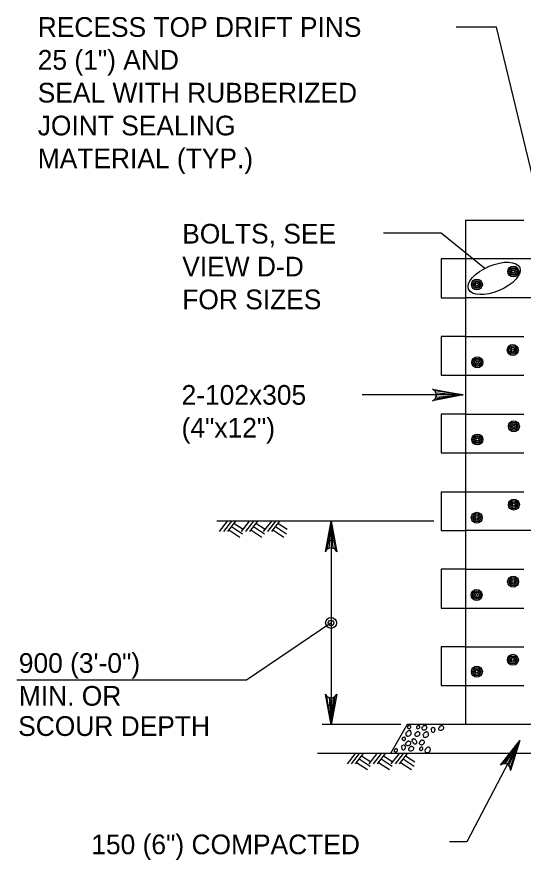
# Model space of a CAD drawing. Extents: x 638142 to 639291, y 297247 to 298438.
# Drawn here: x 638829.2 to 638906.2, y 297993.6 to 298121.9 of the extents above; entities that cross this region are included whole.
import ezdxf

# ---------------------------------------------------------------- set-up
doc = ezdxf.new("R2010")
doc.units = 0
doc.layers.add('3', color=7, linetype='Continuous')
doc.layers.add('5', color=7, linetype='Continuous')

msp = doc.modelspace()

# ---------------------------------------------------------------- linework, layer by layer
at = {"layer": '3'}
for p, q in [((638897.44, 298091), (638906.3, 298091)), ((638897.44, 298091), (638897.44, 298014.22)), ((638897.44, 298085.09), (638893.75, 298085.09)), ((638893.75, 298085.09), (638893.75, 298079.18)), ((638912.21, 298085.09), (638897.44, 298085.09)), ((638893.75, 298079.18), (638897.44, 298079.18)), ((638912.21, 298079.18), (638897.44, 298079.18)), ((638893.75, 298073.28), (638893.75, 298067.37)), ((638897.44, 298073.28), (638893.75, 298073.28)), ((638897.44, 298073.28), (638906.3, 298073.28)), ((638893.75, 298067.37), (638897.44, 298067.37)), ((638897.44, 298067.37), (638906.3, 298067.37)), ((638897.44, 298061.47), (638893.75, 298061.47)), ((638893.75, 298061.47), (638893.75, 298055.56)), ((638897.44, 298061.47), (638906.3, 298061.47)), ((638893.75, 298055.56), (638897.44, 298055.56)), ((638897.44, 298055.56), (638906.3, 298055.56)), ((638893.75, 298049.65), (638893.75, 298043.75)), ((638893.75, 298049.65), (638897.44, 298049.65)), ((638897.44, 298049.65), (638906.3, 298049.65)), ((638892.62, 298045.18), (638859.61, 298045.18)), ((638861.19, 298045.18), (638859.97, 298043.59)), ((638861.82, 298045.18), (638860.6, 298043.59)), ((638862.45, 298045.18), (638861.23, 298043.59)), ((638864.54, 298045.18), (638863.32, 298043.59)), ((638865.17, 298045.18), (638863.95, 298043.59)), ((638865.8, 298045.18), (638864.58, 298043.59)), ((638867.89, 298045.18), (638866.67, 298043.59)), ((638868.52, 298045.18), (638867.29, 298043.59)), ((638869.15, 298045.18), (638867.93, 298043.59)), ((638861.81, 298044.35), (638863.49, 298043.25)), ((638862.2, 298044.85), (638863.58, 298043.94)), ((638865.16, 298044.35), (638866.83, 298043.25)), ((638865.54, 298044.85), (638866.93, 298043.94)), ((638868.51, 298044.35), (638870.18, 298043.25)), ((638868.89, 298044.85), (638870.28, 298043.94)), ((638861.43, 298043.85), (638863.1, 298042.75)), ((638864.77, 298043.85), (638866.45, 298042.75)), ((638868.12, 298043.85), (638869.79, 298042.75)), ((638893.75, 298043.75), (638897.44, 298043.75)), ((638912.21, 298043.75), (638897.44, 298043.75)), ((638897.44, 298037.84), (638893.75, 298037.84)), ((638893.75, 298037.84), (638893.75, 298031.94)), ((638897.44, 298037.84), (638906.3, 298037.84)), ((638893.75, 298031.94), (638897.44, 298031.94)), ((638897.44, 298031.94), (638906.3, 298031.94)), ((638893.75, 298026.03), (638893.75, 298020.13)), ((638897.44, 298026.03), (638893.75, 298026.03)), ((638897.44, 298026.03), (638906.3, 298026.03)), ((638893.75, 298020.13), (638897.44, 298020.13)), ((638897.44, 298020.13), (638906.3, 298020.13)), ((638888.58, 298014.22), (638886.02, 298009.79)), ((638987.5, 298014.22), (638888.58, 298014.22)), ((639000.21, 298009.79), (638874.92, 298009.79)), ((638880.63, 298009.79), (638879.41, 298008.2)), ((638881.26, 298009.79), (638880.04, 298008.2)), ((638881.89, 298009.79), (638880.67, 298008.2)), ((638881.63, 298009.46), (638883.02, 298008.54)), ((638883.97, 298009.79), (638882.75, 298008.2)), ((638884.6, 298009.79), (638883.38, 298008.2)), ((638885.23, 298009.79), (638884.01, 298008.2)), ((638884.98, 298009.46), (638886.36, 298008.54)), ((638887.32, 298009.79), (638886.1, 298008.2)), ((638887.95, 298009.79), (638886.73, 298008.2)), ((638888.58, 298009.79), (638887.36, 298008.2)), ((638888.32, 298009.46), (638889.71, 298008.54)), ((638880.86, 298008.45), (638882.54, 298007.35)), ((638881.25, 298008.96), (638882.92, 298007.86)), ((638884.21, 298008.45), (638885.88, 298007.35)), ((638884.59, 298008.96), (638886.27, 298007.86)), ((638887.56, 298008.45), (638889.23, 298007.35)), ((638887.94, 298008.96), (638889.61, 298007.86))]:
    msp.add_line(p, q, dxfattribs=at)
for centre, radius in [((638904.71, 298083.18), 0.833), ((638904.71, 298083.18), 0.625), ((638904.71, 298083.18), 0.417), ((638904.71, 298083.18), 0.208), ((638899.17, 298081.2), 0.833), ((638899.17, 298081.2), 0.625), ((638899.17, 298081.2), 0.417), ((638899.17, 298081.2), 0.208), ((638904.63, 298071.22), 0.833), ((638904.63, 298071.22), 0.625), ((638904.63, 298071.22), 0.417), ((638904.63, 298071.22), 0.208), ((638899.24, 298069.35), 0.833), ((638899.24, 298069.35), 0.625), ((638899.24, 298069.35), 0.417), ((638899.24, 298069.35), 0.208), ((638904.8, 298059.6), 0.833), ((638904.8, 298059.6), 0.625), ((638904.8, 298059.6), 0.417), ((638904.8, 298059.6), 0.208), ((638899.24, 298057.6), 0.833), ((638899.24, 298057.6), 0.625), ((638899.24, 298057.6), 0.417), ((638899.24, 298057.6), 0.208), ((638904.8, 298047.69), 0.833), ((638904.8, 298047.69), 0.625), ((638904.8, 298047.69), 0.417), ((638904.8, 298047.69), 0.208), ((638899.16, 298045.69), 0.833), ((638899.16, 298045.69), 0.625), ((638899.16, 298045.69), 0.417), ((638899.16, 298045.69), 0.208), ((638904.69, 298035.95), 0.833), ((638904.69, 298035.95), 0.625), ((638904.69, 298035.95), 0.417), ((638904.69, 298035.95), 0.208), ((638899.13, 298033.93), 0.833), ((638899.13, 298033.93), 0.625), ((638899.13, 298033.93), 0.417), ((638899.13, 298033.93), 0.208), ((638904.65, 298024.06), 0.833), ((638904.65, 298024.06), 0.625), ((638904.65, 298024.06), 0.417), ((638904.65, 298024.06), 0.208), ((638899.17, 298022.26), 0.833), ((638899.17, 298022.26), 0.625), ((638899.17, 298022.26), 0.417), ((638899.17, 298022.26), 0.208)]:
    msp.add_circle(centre, radius, dxfattribs=at)
for centre, radius, start, end in [((638889.19, 298012.33), 1, 127.3314, 141.3377), ((638889.33, 298012.15), 1.23, 118.2986, 127.3314), ((638888.78, 298013.8), 0.187, 146.3076, 194.0029), ((638888.82, 298013.81), 0.229, 194.0029, 221.1884), ((638888.81, 298013.78), 0.218, 102.2565, 146.3076), ((638888.84, 298013.82), 0.247, 221.1884, 247.3407), ((638888.91, 298013.84), 0.234, 97.1244, 143.8595), ((638888.85, 298013.86), 0.285, 247.3407, 278.1294), ((638888.91, 298012.92), 0.358, 101.4986, 118.2986), ((638888.89, 298013.02), 0.256, 68.9642, 101.4986), ((638888.9, 298013.87), 0.198, 46.1387, 97.1244), ((638888.85, 298013.83), 0.259, 278.1294, 310.4731), ((638888.89, 298013.01), 0.273, 37.4711, 68.9642), ((638888.83, 298013.86), 0.303, 310.4731, 335.5541), ((638888.84, 298013.81), 0.29, 26.5671, 46.1387), ((638888.91, 298013.84), 0.212, 3.6256, 26.5671), ((638888.88, 298013.84), 0.243, 335.5541, 3.6256), ((638888.82, 298012.95), 0.357, 18.4365, 37.4711), ((638890.17, 298013.8), 0.187, 146.3076, 194.0029), ((638890.21, 298013.81), 0.229, 194.0029, 221.1884), ((638890.2, 298013.78), 0.218, 102.2565, 146.3076), ((638890.15, 298012.7), 0.387, 90, 108.9149), ((638890.22, 298013.82), 0.247, 221.1884, 247.3407), ((638890.3, 298013.84), 0.234, 97.1244, 143.8595), ((638890.24, 298013.86), 0.285, 247.3407, 278.1294), ((638890.15, 298012.64), 0.454, 72.5511, 90), ((638890.29, 298013.87), 0.198, 46.1387, 97.1244), ((638890.24, 298013.83), 0.259, 278.1294, 310.4731), ((638890.21, 298013.86), 0.303, 310.4731, 335.5541), ((638890.23, 298013.81), 0.29, 26.5671, 46.1387), ((638890.3, 298013.84), 0.212, 3.6256, 26.5671), ((638890.27, 298013.84), 0.243, 335.5541, 3.6256), ((638890.96, 298013.62), 0.187, 143.9702, 187.7584), ((638890.95, 298013.62), 0.181, 187.7584, 225.0025), ((638890.99, 298013.6), 0.227, 104.4085, 143.9702), ((638891.13, 298013.8), 0.433, 225.0025, 248.8171), ((638891.25, 298013.72), 0.35, 140.7081, 167.2711), ((638891.12, 298013.77), 0.402, 248.8171, 282.2637), ((638891.17, 298013.78), 0.246, 108.9149, 140.7081), ((638891.22, 298013.65), 0.387, 90, 108.9149), ((638891.1, 298013.87), 0.508, 282.2637, 311.9318), ((638891.22, 298013.58), 0.454, 72.5511, 90), ((638891.24, 298013.65), 0.383, 47.7288, 72.5511), ((638891.07, 298013.9), 0.547, 311.9318, 336.3688), ((638891.3, 298013.72), 0.289, 19.08, 47.7288), ((638891.4, 298013.75), 0.185, 336.3688, 19.08), ((638892.45, 298013.45), 0.265, 134.9029, 173.2896), ((638892.5, 298013.44), 0.311, 173.2896, 208.6507), ((638892.52, 298013.29), 0.292, 187.256, 209.0568), ((638892.48, 298013.27), 0.244, 209.0568, 232.9021), ((638892.51, 298013.4), 0.338, 104.0351, 134.9029), ((638892.49, 298013.45), 0.286, 70.3851, 104.0351), ((638892.29, 298013.51), 0.555, 300.2542, 319.7493), ((638892.47, 298013.4), 0.343, 45.0025, 70.3851), ((638892.39, 298013.43), 0.418, 319.7493, 347.4701), ((638892.5, 298013.42), 0.303, 17.9593, 45.0025), ((638892.46, 298013.41), 0.347, 347.4701, 17.9593), ((638893.52, 298013.58), 0.187, 143.9702, 187.7584), ((638893.51, 298013.58), 0.181, 187.7584, 225.0025), ((638893.55, 298013.56), 0.227, 104.4085, 143.9702), ((638893.69, 298013.76), 0.433, 225.0025, 248.8171), ((638893.82, 298013.68), 0.35, 140.7081, 167.2711), ((638893.68, 298013.73), 0.402, 248.8171, 282.2637), ((638893.74, 298013.75), 0.246, 108.9149, 140.7081), ((638893.78, 298013.61), 0.387, 90, 108.9149), ((638893.66, 298013.83), 0.508, 282.2637, 311.9318), ((638893.78, 298013.55), 0.454, 72.5511, 90), ((638893.8, 298013.61), 0.383, 47.7288, 72.5511), ((638893.63, 298013.86), 0.547, 311.9318, 336.3688), ((638893.87, 298013.68), 0.289, 19.08, 47.7288), ((638893.96, 298013.72), 0.185, 336.3688, 19.08), ((638887.98, 298012.01), 0.187, 146.3076, 194.0029), ((638888.02, 298012.02), 0.229, 194.0029, 221.1884), ((638888, 298011.99), 0.218, 102.2565, 146.3076), ((638888.03, 298012.03), 0.247, 221.1884, 247.3407), ((638888.1, 298012.05), 0.234, 97.1244, 143.8595), ((638888.05, 298012.07), 0.285, 247.3407, 278.1294), ((638888.1, 298012.08), 0.198, 46.1387, 97.1244), ((638888.05, 298012.04), 0.259, 278.1294, 310.4731), ((638888.02, 298012.07), 0.303, 310.4731, 335.5541), ((638888.04, 298012.02), 0.29, 26.5671, 46.1387), ((638888.11, 298012.05), 0.212, 3.6256, 26.5671), ((638888.08, 298012.05), 0.243, 335.5541, 3.6256), ((638888.47, 298012.79), 0.14, 164.7784, 205.3396), ((638888.69, 298012.73), 0.361, 141.3377, 164.7784), ((638888.69, 298012.9), 0.382, 205.3396, 229.5229), ((638888.72, 298012.73), 0.348, 203.6387, 219.8081), ((638888.56, 298012.59), 0.138, 219.8081, 245.6186), ((638888.61, 298012.71), 0.266, 245.6186, 273.3662), ((638888.58, 298013.24), 0.798, 273.3662, 289.2839), ((638888.54, 298013.36), 0.926, 289.2839, 302.7329), ((638888.88, 298012.83), 0.294, 302.7329, 326.7251), ((638888.84, 298012.85), 0.333, 326.7251, 347.0043), ((638888.69, 298012.91), 0.498, 2.3392, 18.4365), ((638888.6, 298012.91), 0.579, 347.0043, 2.3392), ((638889.61, 298011.67), 0.366, 129.47, 171.7294), ((638889.53, 298011.76), 0.252, 77.9637, 129.47), ((638889.45, 298011.39), 0.632, 65.558, 77.9637), ((638889.89, 298012.67), 0.187, 143.9702, 187.7584), ((638889.89, 298012.67), 0.181, 187.7584, 225.0025), ((638889.55, 298011.6), 0.398, 49.9215, 65.558), ((638889.92, 298012.65), 0.227, 104.4085, 143.9702), ((638890.06, 298012.85), 0.433, 225.0025, 248.8171), ((638889.35, 298011.36), 0.712, 35.5401, 49.9215), ((638890.19, 298012.77), 0.35, 140.7081, 167.2711), ((638890.05, 298012.82), 0.402, 248.8171, 282.2637), ((638890.11, 298012.84), 0.246, 108.9149, 140.7081), ((638890.03, 298012.93), 0.508, 282.2637, 311.9318), ((638890.17, 298012.71), 0.383, 47.7288, 72.5511), ((638890, 298012.95), 0.547, 311.9318, 336.3688), ((638890.24, 298012.77), 0.289, 19.08, 47.7288), ((638890.34, 298012.81), 0.185, 336.3688, 19.08), ((638890.84, 298011.42), 0.387, 90, 108.9149), ((638890.84, 298011.35), 0.454, 72.5511, 90), ((638891.32, 298012.53), 0.361, 141.3377, 164.7784), ((638891.11, 298012.59), 0.14, 164.7784, 205.3396), ((638891.33, 298012.7), 0.382, 205.3396, 229.5229), ((638891.35, 298012.53), 0.348, 203.6387, 219.8081), ((638891.82, 298012.13), 1, 127.3314, 141.3377), ((638891.19, 298012.39), 0.138, 219.8081, 245.6186), ((638891.24, 298012.51), 0.266, 245.6186, 273.3662), ((638891.96, 298011.95), 1.23, 118.2986, 127.3314), ((638891.21, 298013.04), 0.798, 273.3662, 289.2839), ((638891.55, 298012.72), 0.358, 101.4986, 118.2986), ((638891.53, 298012.82), 0.256, 68.9642, 101.4986), ((638891.17, 298013.16), 0.926, 289.2839, 302.7329), ((638891.52, 298012.8), 0.273, 37.4711, 68.9642), ((638891.51, 298012.63), 0.294, 302.7329, 326.7251), ((638891.45, 298012.75), 0.357, 18.4365, 37.4711), ((638891.48, 298012.65), 0.333, 326.7251, 347.0043), ((638891.32, 298012.71), 0.498, 2.3392, 18.4365), ((638891.24, 298012.7), 0.579, 347.0043, 2.3392), ((638892.53, 298013.35), 0.343, 232.9021, 246.8032), ((638892.5, 298013.27), 0.256, 246.8032, 262.9077), ((638892.49, 298013.17), 0.155, 262.9077, 300.2542), ((638886.9, 298010.3), 0.234, 97.1244, 143.8595), ((638886.89, 298010.33), 0.198, 46.1387, 97.1244), ((638887.96, 298010.77), 0.265, 134.9029, 173.2896), ((638888.01, 298010.77), 0.311, 173.2896, 208.6507), ((638888.02, 298010.61), 0.292, 187.256, 209.0568), ((638888.01, 298010.72), 0.338, 104.0351, 134.9029), ((638888, 298010.77), 0.286, 70.3851, 104.0351), ((638887.98, 298010.72), 0.343, 45.0025, 70.3851), ((638888.01, 298010.74), 0.303, 17.9593, 45.0025), ((638887.9, 298010.75), 0.418, 319.7493, 347.4701), ((638887.97, 298010.73), 0.347, 347.4701, 17.9593), ((638888.5, 298011.25), 0.187, 143.9702, 187.7584), ((638888.5, 298011.24), 0.181, 187.7584, 225.0025), ((638888.54, 298011.22), 0.227, 104.4085, 143.9702), ((638888.68, 298011.42), 0.433, 225.0025, 248.8171), ((638888.8, 298011.34), 0.35, 140.7081, 167.2711), ((638888.66, 298011.39), 0.402, 248.8171, 282.2637), ((638888.72, 298011.41), 0.246, 108.9149, 140.7081), ((638888.77, 298011.28), 0.387, 90, 108.9149), ((638888.64, 298011.5), 0.508, 282.2637, 311.9318), ((638888.95, 298010.44), 0.187, 143.9702, 187.7584), ((638888.77, 298011.21), 0.454, 72.5511, 90), ((638888.98, 298010.42), 0.227, 104.4085, 143.9702), ((638888.79, 298011.28), 0.383, 47.7288, 72.5511), ((638889.24, 298010.54), 0.35, 140.7081, 167.2711), ((638889.16, 298010.61), 0.246, 108.9149, 140.7081), ((638888.62, 298011.53), 0.547, 311.9318, 336.3688), ((638888.85, 298011.35), 0.289, 19.08, 47.7288), ((638889.21, 298010.47), 0.387, 90, 108.9149), ((638888.95, 298011.38), 0.185, 336.3688, 19.08), ((638889.21, 298010.4), 0.454, 72.5511, 90), ((638888.08, 298010.26), 1.83, 45.0025, 49.7663), ((638889.23, 298010.47), 0.383, 47.7288, 72.5511), ((638888.4, 298010.58), 1.38, 39.5094, 45.0025), ((638888.67, 298010.81), 1.03, 32.5518, 39.5094), ((638889.29, 298010.54), 0.289, 19.08, 47.7288), ((638889.86, 298011.57), 0.384, 212.5518, 223.9474), ((638889.39, 298010.58), 0.185, 336.3688, 19.08), ((638889.67, 298011.38), 0.116, 223.9474, 259.696), ((638889.75, 298011.83), 0.576, 259.696, 275.5269), ((638889.77, 298011.63), 0.368, 275.5269, 296.563), ((638889.4, 298011.39), 0.652, 20.509, 35.5401), ((638889.85, 298011.47), 0.188, 296.563, 326.1765), ((638889.57, 298011.46), 0.468, 0, 20.509), ((638889.86, 298011.46), 0.175, 326.1765, 0), ((638890.58, 298011.39), 0.187, 143.9702, 187.7584), ((638890.57, 298011.39), 0.181, 187.7584, 225.0025), ((638890.61, 298011.36), 0.227, 104.4085, 143.9702), ((638890.61, 298010.5), 0.187, 146.3076, 194.0029), ((638890.75, 298011.56), 0.433, 225.0025, 248.8171), ((638890.64, 298010.48), 0.218, 102.2565, 146.3076), ((638890.87, 298011.48), 0.35, 140.7081, 167.2711), ((638890.74, 298010.54), 0.234, 97.1244, 143.8595), ((638890.74, 298011.53), 0.402, 248.8171, 282.2637), ((638890.79, 298011.55), 0.246, 108.9149, 140.7081), ((638890.74, 298010.57), 0.198, 46.1387, 97.1244), ((638890.71, 298011.64), 0.508, 282.2637, 311.9318), ((638890.67, 298010.51), 0.29, 26.5671, 46.1387), ((638890.74, 298010.54), 0.212, 3.6256, 26.5671), ((638890.71, 298010.54), 0.243, 335.5541, 3.6256), ((638890.86, 298011.42), 0.383, 47.7288, 72.5511), ((638890.69, 298011.67), 0.547, 311.9318, 336.3688), ((638890.92, 298011.49), 0.289, 19.08, 47.7288), ((638891.02, 298011.52), 0.185, 336.3688, 19.08), ((638892.1, 298009.81), 1, 127.3314, 141.3377), ((638892.24, 298009.63), 1.23, 118.2986, 127.3314), ((638891.82, 298010.4), 0.358, 101.4986, 118.2986), ((638891.8, 298010.5), 0.256, 68.9642, 101.4986), ((638891.8, 298010.48), 0.273, 37.4711, 68.9642), ((638891.73, 298010.43), 0.357, 18.4365, 37.4711), ((638891.6, 298010.39), 0.498, 2.3392, 18.4365), ((638886.77, 298010.26), 0.187, 146.3076, 194.0029), ((638886.81, 298010.27), 0.229, 194.0029, 221.1884), ((638886.8, 298010.24), 0.218, 102.2565, 146.3076), ((638886.82, 298010.28), 0.247, 221.1884, 247.3407), ((638886.84, 298010.32), 0.285, 247.3407, 278.1294), ((638886.84, 298010.29), 0.259, 278.1294, 310.4731), ((638886.81, 298010.32), 0.303, 310.4731, 335.5541), ((638886.83, 298010.27), 0.29, 26.5671, 46.1387), ((638886.9, 298010.3), 0.212, 3.6256, 26.5671), ((638886.87, 298010.3), 0.243, 335.5541, 3.6256), ((638887.98, 298010.59), 0.244, 209.0568, 232.9021), ((638888.04, 298010.67), 0.343, 232.9021, 246.8032), ((638888.01, 298010.59), 0.256, 246.8032, 262.9077), ((638888, 298010.49), 0.155, 262.9077, 300.2542), ((638887.79, 298010.83), 0.555, 300.2542, 319.7493), ((638888.94, 298010.44), 0.181, 187.7584, 225.0025), ((638889.12, 298010.62), 0.433, 225.0025, 248.8171), ((638889.11, 298010.59), 0.402, 248.8171, 282.2637), ((638889.08, 298010.69), 0.508, 282.2637, 311.9318), ((638889.06, 298010.72), 0.547, 311.9318, 336.3688), ((638890.65, 298010.51), 0.229, 194.0029, 221.1884), ((638890.67, 298010.52), 0.247, 221.1884, 247.3407), ((638890.68, 298010.56), 0.285, 247.3407, 278.1294), ((638890.68, 298010.53), 0.259, 278.1294, 310.4731), ((638890.66, 298010.57), 0.303, 310.4731, 335.5541), ((638891.38, 298010.27), 0.14, 164.7784, 205.3396), ((638891.6, 298010.21), 0.361, 141.3377, 164.7784), ((638891.6, 298010.37), 0.382, 205.3396, 229.5229), ((638891.63, 298010.2), 0.348, 203.6387, 219.8081), ((638891.47, 298010.07), 0.138, 219.8081, 245.6186), ((638891.52, 298010.19), 0.266, 245.6186, 273.3662), ((638891.49, 298010.72), 0.798, 273.3662, 289.2839), ((638891.45, 298010.84), 0.926, 289.2839, 302.7329), ((638891.79, 298010.31), 0.294, 302.7329, 326.7251), ((638891.75, 298010.33), 0.333, 326.7251, 347.0043), ((638891.51, 298010.38), 0.579, 347.0043, 2.3392)]:
    msp.add_arc(centre, radius, start, end, dxfattribs=at)
at = {"layer": '5'}
for p, q in [((638876.98, 298045.18), (638876.98, 298014.18)), ((638876.98, 298029.68), (638864.11, 298020.97)), ((638864.11, 298020.97), (638829.16, 298020.97)), ((638887.58, 298014.22), (638875.63, 298014.22)), ((638905.69, 298011.76), (638897.63, 297996.34)), ((638897.63, 297996.34), (638895.01, 297996.34))]:
    msp.add_line(p, q, dxfattribs=at)
for points in [[(638909.25, 298091), (638902.15, 298120.35), (638896.04, 298120.35)], [(638900.36, 298083.65), (638893.72, 298089.02), (638884.96, 298089.02)], [(638897.07, 298064.38), (638892.41, 298063.51), (638892.77, 298063.76), (638892.95, 298064.07), (638893.01, 298064.38), (638892.95, 298064.7), (638892.77, 298065.01), (638892.41, 298065.26), (638897.07, 298064.38), (638892.77, 298065.01), (638892.95, 298064.7), (638897.07, 298064.38), (638893.01, 298064.38), (638892.95, 298064.07), (638897.07, 298064.38), (638892.77, 298063.76)], [(638897.07, 298064.38), (638881.72, 298064.38)], [(638876.98, 298045.18), (638877.86, 298040.52), (638877.61, 298040.88), (638877.3, 298041.07), (638876.98, 298041.12), (638876.67, 298041.07), (638876.36, 298040.88), (638876.11, 298040.52), (638876.98, 298045.18), (638876.36, 298040.88), (638876.67, 298041.07), (638876.98, 298045.18), (638876.98, 298041.12), (638877.3, 298041.07), (638876.98, 298045.18), (638877.61, 298040.88)], [(638876.98, 298014.18), (638876.11, 298018.84), (638876.36, 298018.48), (638876.67, 298018.3), (638876.98, 298018.24), (638877.3, 298018.3), (638877.61, 298018.48), (638877.86, 298018.84), (638876.98, 298014.18), (638877.61, 298018.48), (638877.3, 298018.3), (638876.98, 298014.18), (638876.98, 298018.24), (638876.67, 298018.3), (638876.98, 298014.18), (638876.36, 298018.48)], [(638905.69, 298011.76), (638904.3, 298007.22), (638904.25, 298007.65), (638904.06, 298007.96), (638903.81, 298008.16), (638903.51, 298008.25), (638903.14, 298008.23), (638902.76, 298008.03), (638905.69, 298011.76), (638903.14, 298008.23), (638903.51, 298008.25), (638905.69, 298011.76), (638903.81, 298008.16), (638904.06, 298007.96), (638905.69, 298011.76), (638904.25, 298007.65)]]:
    msp.add_lwpolyline(points, dxfattribs=at)
for points in [[(638876.49, 298042.23), (638877.47, 298042.23), (638876.98, 298045.18)], [(638876.49, 298017.13), (638877.47, 298017.13), (638876.98, 298014.18)], [(638903.89, 298009.37), (638904.76, 298008.91), (638905.69, 298011.76)]]:
    msp.add_lwpolyline(points, close=True, dxfattribs=at)
for radius in [0.833, 0.417]:
    msp.add_circle((638876.98, 298029.68), radius, dxfattribs=at)
msp.add_ellipse((638901.8, 298082.13), major_axis=(3.89, 1.64), ratio=0.473013, dxfattribs=at)

# ---------------------------------------------------------------- texts
for s, height, p in [('RECESS TOP DRIFT PINS', 3.0001, (638832.34, 298118.9)), ('25 (1") AND', 3.0001, (638832.34, 298113.9)), ('SEAL WITH RUBBERIZED', 3.0001, (638832.34, 298108.9)), ('JOINT SEALING', 3.0001, (638832.34, 298103.9)), ('MATERIAL (TYP.)', 3.0001, (638832.34, 298098.9)), ('BOLTS, SEE', 3, (638854.33, 298087.43)), ('VIEW D-D', 3, (638854.33, 298082.43)), ('FOR SIZES', 3, (638854.33, 298077.43)), ('2-102x305', 3, (638854.23, 298062.89)), ('(4"x12")', 3, (638854.23, 298057.89)), ('900 (3\'-0")', 3.0001, (638829.46, 298022.07)), ('MIN. OR', 3, (638829.46, 298017.07)), ('SCOUR DEPTH', 3.0001, (638829.36, 298012.47)), ('150 (6") COMPACTED', 3.0001, (638840.49, 297994.46))]:
    msp.add_text(s, height=height, dxfattribs=at).set_placement(p)

doc.saveas('drawing.dxf')
